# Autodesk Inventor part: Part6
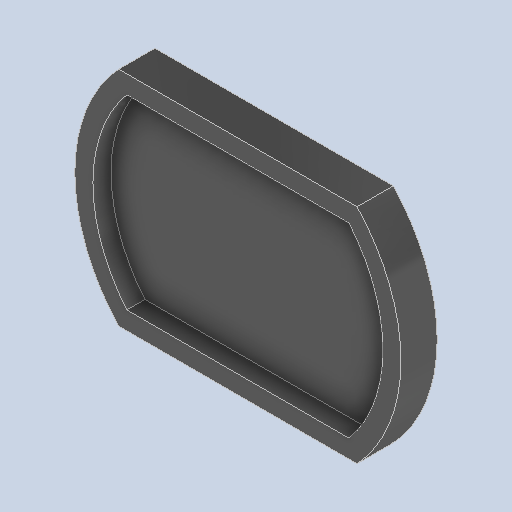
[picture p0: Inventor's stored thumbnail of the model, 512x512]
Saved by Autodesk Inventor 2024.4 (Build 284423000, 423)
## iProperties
Created: 2025-04
Part Number: Part6
Material: Generic
Document SubType Name: Modeling
Designer: AdminForWorker
Density: 1 g/cm^3
Appearance: Default
Author: AdminForWorker
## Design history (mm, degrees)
feature "Body1"
body "Solid1"
